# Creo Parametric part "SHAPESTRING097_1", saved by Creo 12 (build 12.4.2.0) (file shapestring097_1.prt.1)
Units: Custom; MM, KILOGRAM, SECS

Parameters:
  PTC_WM_ITERATION = "0"
  PTC_WM_VERSION = "-.0"
  PTC_WM_LIFECYCLE_STATE = "In Work"
  PTC_WM_LIFECYCLE = "MO_CADDocument"
  PTC_WM_CREATED_BY = "Maximilian Roepper (Z0017RMS: MO)"
  PTC_WM_CREATED_ON = "18-Sep-26 11:36:42 AM"
  PTC_WM_MODIFIED_BY = "Maximilian Roepper (Z0017RMS: MO)"
  PTC_WM_MODIFIED_ON = "18-Sep-26 11:36:46 AM"
  PDMLINKNUMBER = "PDM000071454927"
  PTC_WM_NAME = "shapestring097_1.prt"
  PTC_WM_NUMBER = "PDM000071454927"

Other parameters: WEIGHT, WEIGHT_FACTOR, WEIGHT_ADD, _MASS_TEMP, _DIFF_TEMP, MC_ERRORS, SUPPLIER

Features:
  1. coordinate system
  2. datum plane "PRT_YZ"
  3. datum plane "PRT_XY"
  4. datum plane "PRT_XZ"
  5. coordinate system
  6. datum axis
  7. datum axis
  8. datum axis
  9. coordinate system
  10. imported feature
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
Other named items: PRT, SIEMENS_MO, DRW_VIEW_ORG, PRT_X, PRT_Y, PRT_Z, CS0, ROUGH_GROB

Layers: 00_STD_CSYS-KSYS, 01_STD_PLANES-EBENEN, 02_STD_AXES-ACHSEN, 03_STD_CSYS-KSYS, 24_IMPORT_FEAT-IMPORT_KE, INTFCLR

Surfaces: 1 plane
